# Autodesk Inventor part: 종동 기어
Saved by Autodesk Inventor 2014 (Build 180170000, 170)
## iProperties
Created: 2025-12
Part Number: 종동 기어
Material: 일반
Document SubType Name: Modeling
Designer: dg
Density: 1 g/cm^3
Appearance: 기본값
Author: dg
Author: jhkim
Creation Date: 2025-11-19
Sending System: Autodesk Inventor 2026
Preprocessor: ST-DEVELOPER v20.1
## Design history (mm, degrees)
node "종동 기어1"
node "솔리드1"
node "기준1"
